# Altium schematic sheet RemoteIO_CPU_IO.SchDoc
size 431 x 279 mm; Date: Not shown in title block; ApprovedBy: Not shown in title block; CheckedBy: Not shown in title block; Author: Not shown in title block; CompanyName: Not shown in title block; Engineer: Not shown in title block; Organization: Not shown in title block; Address1: Not shown in title block; Address2: Not shown in title block; Address3: Not shown in title block; Address4: Not shown in title block; DocumentNumber: 5; Revision: Use project parameter SCH_Rev; SheetNumber: 5; SheetTotal: 14; PageSetup: Record=PageOptions¦CenterHorizontal=True¦CenterVertical=True¦PrintScale=1.00¦XCorrection=1.00¦YCorrection=1.00¦PrintKind=0¦BorderSize=5000000¦LeftOffset=0¦BottomOffset=0¦Orientation=2¦PaperLength=1000¦PaperWidth=1000¦Scale=100¦PaperSource=15¦PrintQuality=600¦MediaType=1¦DitherType=10¦PaperKind=Letter¦PrintScaleMode=1
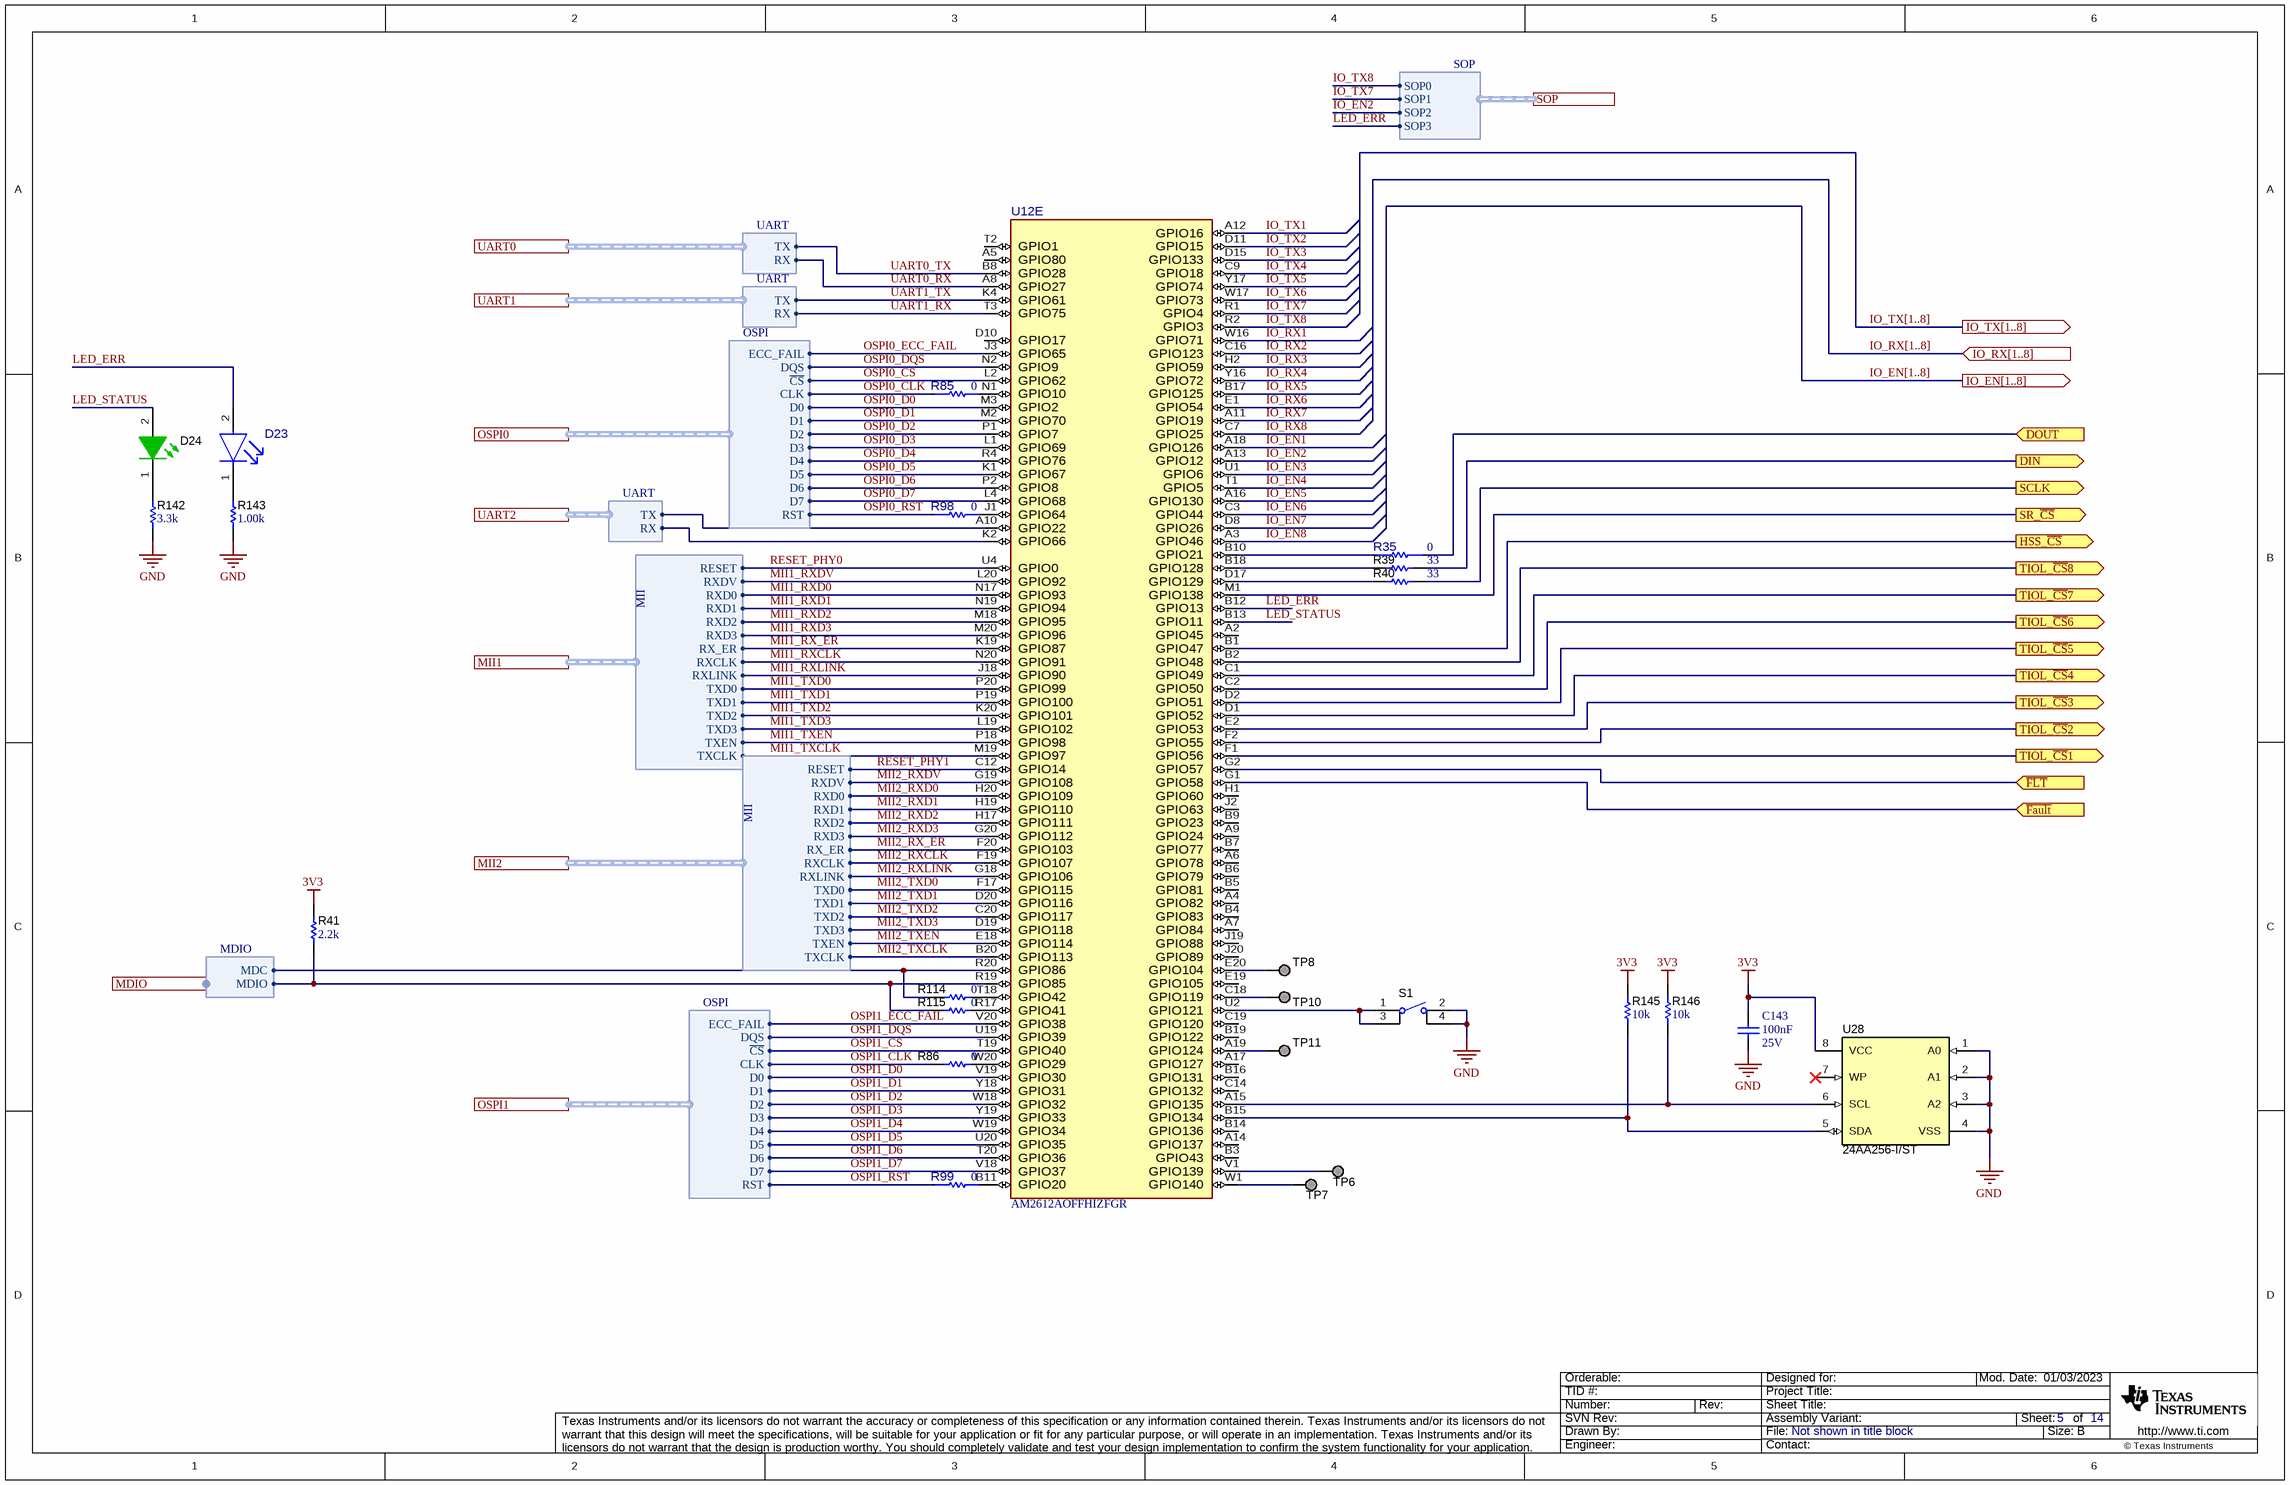
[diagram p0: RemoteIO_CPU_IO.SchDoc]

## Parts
C143  Cap_F: 100nF  Rated Voltage (DC): 25V  [WCAP-CSGP_0402_L1W0.5H0.5]  (hidden comment: 885012105018)
D23  150040RS73240  [FP-150040RS73220_0402-MFG]  (value not drawn)
D24  150040GS73240  [WL-SMCC_0402_Green]  (value not drawn)
R35  value 0  [FP-CRCW04020000Z0EDC_0402-MFG]  (hidden comment: CRCW04020000Z0EDC)
R39  ValueDisplayed: 33  [0402]  (hidden comment: CRCW040233R0JNED)
R40  ValueDisplayed: 33  [0402]  (hidden comment: CRCW040233R0JNED)
R41  ValueDisplayed: 2.2k  [0402]  (hidden comment: CRCW04022K20JNED)
R85  value 0  [FP-CRCW04020000Z0EDC_0402-MFG]  (hidden comment: CRCW04020000Z0EDC)
R86  ValueDisplayed: 0  [0201L]  (hidden comment: CRCW02010000Z0ED)
R98  value 0  [FP-CRCW04020000Z0EDC_0402-MFG]  (hidden comment: CRCW04020000Z0EDC)
R99  value 0  [FP-CRCW04020000Z0EDC_0402-MFG]  (hidden comment: CRCW04020000Z0EDC)
R114  ValueDisplayed: 0  [0201L]  (hidden comment: CRCW02010000Z0ED)
R115  ValueDisplayed: 0  [0201L]  (hidden comment: CRCW02010000Z0ED)
R142  ValueDisplayed: 3.3k  [0402]  (hidden comment: CRCW04023K30JNED)
R143  ValueDisplayed: 1.00k  [0402]  (hidden comment: CRCW04021K00FKED)
R145  ValueDisplayed: 10k  [0402]  (hidden comment: CRCW040210K0JNED)
R146  ValueDisplayed: 10k  [0402]  (hidden comment: CRCW040210K0JNED)
S1  434153017835  [SW_434153017835]  (value not drawn)
TP6  TESTPOINT  [TP_25MIL-SMT]  (value not drawn)  (no BOM)
TP7  TESTPOINT  [TP_25MIL-SMT]  (value not drawn)  (no BOM)
TP8  TESTPOINT  [TP_25MIL-SMT]  (value not drawn)  (no BOM)
TP10  TESTPOINT  [TP_25MIL-SMT]  (value not drawn)  (no BOM)
TP11  TESTPOINT  [TP_25MIL-SMT]  (value not drawn)  (no BOM)
U12  AM2612AOFFHIZFGR  [ZFG0304A-MFG]  (part E of 7)
U28  24AA256-I/ST  [TSSOP-8]

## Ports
DIN (out), DOUT (in), HSS_~{CS} (out), IO_EN[1..8] (out), IO_RX[1..8] (in), IO_TX[1..8] (out), MDIO (harness MDIO), MII1 (harness MII), MII2 (harness MII), OSPI0 (harness OSPI), OSPI1 (harness OSPI), SCLK (out), SOP (harness SOP), SR_~{CS} (out), TIOL_~{CS}1 (out), TIOL_~{CS}2 (out), TIOL_~{CS}3 (out), TIOL_~{CS}4 (out), TIOL_~{CS}5 (out), TIOL_~{CS}6 (out), TIOL_~{CS}7 (out), TIOL_~{CS}8 (out), UART0 (harness UART), UART1 (harness UART), UART2 (harness UART), ~{Fault} (in), ~{FLT} (in)

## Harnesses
MII: RXDV, RXD0, RXD1, RXD2, RXD3, RX_ER, RXCLK, RXLINK, TXD0, TXD1, TXD2, TXD3, TXEN, TXCLK, RESET
MDIO: MDC, MDIO
UART: TX, RX
OSPI: ~{CS}, CLK, D0, D1, D2, D3, D4, D5, D6, D7, DQS, ECC_FAIL, RST
SOP: SOP0, SOP1, SOP2, SOP3

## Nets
3V3: C143.2 R41.1 R145.1 R146.1 U28.8(VCC)
GND: C143.1 R142.1 R143.1 S1.2 S1.4 U28.1(A0) U28.2(A1) U28.3(A2) U28.4(VSS)
~{Fault}: U12.G1(GPIO58) ; port ~{Fault}
~{FLT}: U12.G2(GPIO57) ; port ~{FLT}
DIN: R39.2 ; port DIN
DOUT: R35.1 ; port DOUT
HSS_~{CS}: U12.B1(GPIO47) ; port HSS_~{CS}
IO_EN1: U12.A18(GPIO126)
IO_EN2: U12.A13(GPIO12) ; port SOP.SOP2
IO_EN3: U12.U1(GPIO6)
IO_EN4: U12.T1(GPIO5)
IO_EN5: U12.A16(GPIO130)
IO_EN6: U12.C3(GPIO44)
IO_EN7: U12.D8(GPIO26)
IO_EN8: U12.A3(GPIO46)
IO_RX1: U12.W16(GPIO71)
IO_RX2: U12.C16(GPIO123)
IO_RX3: U12.H2(GPIO59)
IO_RX4: U12.Y16(GPIO72)
IO_RX5: U12.B17(GPIO125)
IO_RX6: U12.E1(GPIO54)
IO_RX7: U12.A11(GPIO19)
IO_RX8: U12.C7(GPIO25)
IO_TX1: U12.A12(GPIO16)
IO_TX2: U12.D11(GPIO15)
IO_TX3: U12.D15(GPIO133)
IO_TX4: U12.C9(GPIO18)
IO_TX5: U12.Y17(GPIO74)
IO_TX6: U12.W17(GPIO73)
IO_TX7: U12.R1(GPIO4) ; port SOP.SOP1
IO_TX8: U12.R2(GPIO3) ; port SOP.SOP0
LED_ERR: D23.2(ANODE) U12.B12(GPIO13) ; port SOP.SOP3
LED_STATUS: D24.2(A) U12.B13(GPIO11)
MII1_RX_ER: U12.K19(GPIO87) ; port MII1.RX_ER
MII1_RXCLK: U12.N20(GPIO91) ; port MII1.RXCLK
MII1_RXD0: U12.N17(GPIO93) ; port MII1.RXD0
MII1_RXD1: U12.N19(GPIO94) ; port MII1.RXD1
MII1_RXD2: U12.M18(GPIO95) ; port MII1.RXD2
MII1_RXD3: U12.M20(GPIO96) ; port MII1.RXD3
MII1_RXDV: U12.L20(GPIO92) ; port MII1.RXDV
MII1_RXLINK: U12.J18(GPIO90) ; port MII1.RXLINK
MII1_TXCLK: U12.M19(GPIO97) ; port MII1.TXCLK
MII1_TXD0: U12.P20(GPIO99) ; port MII1.TXD0
MII1_TXD1: U12.P19(GPIO100) ; port MII1.TXD1
MII1_TXD2: U12.K20(GPIO101) ; port MII1.TXD2
MII1_TXD3: U12.L19(GPIO102) ; port MII1.TXD3
MII1_TXEN: U12.P18(GPIO98) ; port MII1.TXEN
MII2_RX_ER: U12.F20(GPIO103) ; port MII2.RX_ER
MII2_RXCLK: U12.F19(GPIO107) ; port MII2.RXCLK
MII2_RXD0: U12.H20(GPIO109) ; port MII2.RXD0
MII2_RXD1: U12.H19(GPIO110) ; port MII2.RXD1
MII2_RXD2: U12.H17(GPIO111) ; port MII2.RXD2
MII2_RXD3: U12.G20(GPIO112) ; port MII2.RXD3
MII2_RXDV: U12.G19(GPIO108) ; port MII2.RXDV
MII2_RXLINK: U12.G18(GPIO106) ; port MII2.RXLINK
MII2_TXCLK: U12.B20(GPIO113) ; port MII2.TXCLK
MII2_TXD0: U12.F17(GPIO115) ; port MII2.TXD0
MII2_TXD1: U12.D20(GPIO116) ; port MII2.TXD1
MII2_TXD2: U12.C20(GPIO117) ; port MII2.TXD2
MII2_TXD3: U12.D19(GPIO118) ; port MII2.TXD3
MII2_TXEN: U12.E18(GPIO114) ; port MII2.TXEN
OSPI0_~{CS}: U12.L2(GPIO62) ; port OSPI0.~{CS}
OSPI0_CLK: R85.1 ; port OSPI0.CLK
OSPI0_D0: U12.M3(GPIO2) ; port OSPI0.D0
OSPI0_D1: U12.M2(GPIO70) ; port OSPI0.D1
OSPI0_D2: U12.P1(GPIO7) ; port OSPI0.D2
OSPI0_D3: U12.L1(GPIO69) ; port OSPI0.D3
OSPI0_D4: U12.R4(GPIO76) ; port OSPI0.D4
OSPI0_D5: U12.K1(GPIO67) ; port OSPI0.D5
OSPI0_D6: U12.P2(GPIO8) ; port OSPI0.D6
OSPI0_D7: U12.L4(GPIO68) ; port OSPI0.D7
OSPI0_DQS: U12.N2(GPIO9) ; port OSPI0.DQS
OSPI0_ECC_FAIL: U12.J3(GPIO65) ; port OSPI0.ECC_FAIL
OSPI0_RST: R98.1 ; port OSPI0.RST
OSPI1_~{CS}: U12.T19(GPIO40) ; port OSPI1.~{CS}
OSPI1_CLK: R86.1 ; port OSPI1.CLK
OSPI1_D0: U12.V19(GPIO30) ; port OSPI1.D0
OSPI1_D1: U12.Y18(GPIO31) ; port OSPI1.D1
OSPI1_D2: U12.W18(GPIO32) ; port OSPI1.D2
OSPI1_D3: U12.Y19(GPIO33) ; port OSPI1.D3
OSPI1_D4: U12.W19(GPIO34) ; port OSPI1.D4
OSPI1_D5: U12.U20(GPIO35) ; port OSPI1.D5
OSPI1_D6: U12.T20(GPIO36) ; port OSPI1.D6
OSPI1_D7: U12.V18(GPIO37) ; port OSPI1.D7
OSPI1_DQS: U12.U19(GPIO39) ; port OSPI1.DQS
OSPI1_ECC_FAIL: U12.V20(GPIO38) ; port OSPI1.ECC_FAIL
OSPI1_RST: R99.1 ; port OSPI1.RST
RESET_PHY0: U12.U4(GPIO0) ; port MII1.RESET
RESET_PHY1: U12.C12(GPIO14) ; port MII2.RESET
SCLK: R40.2 ; port SCLK
SR_~{CS}: U12.M1(GPIO138) ; port SR_~{CS}
TIOL_~{CS}1: U12.F1(GPIO56) ; port TIOL_~{CS}1
TIOL_~{CS}2: U12.F2(GPIO55) ; port TIOL_~{CS}2
TIOL_~{CS}3: U12.E2(GPIO53) ; port TIOL_~{CS}3
TIOL_~{CS}4: U12.D1(GPIO52) ; port TIOL_~{CS}4
TIOL_~{CS}5: U12.D2(GPIO51) ; port TIOL_~{CS}5
TIOL_~{CS}6: U12.C2(GPIO50) ; port TIOL_~{CS}6
TIOL_~{CS}7: U12.C1(GPIO49) ; port TIOL_~{CS}7
TIOL_~{CS}8: U12.B2(GPIO48) ; port TIOL_~{CS}8
UART0_RX: U12.A8(GPIO27) ; port UART0.RX
UART0_TX: U12.B8(GPIO28) ; port UART0.TX
UART1_RX: U12.T3(GPIO75) ; port UART1.RX
UART1_TX: U12.K4(GPIO61) ; port UART1.TX
NetD23_1: D23.1(CATHODE) R143.2
NetD24_1: D24.1(K) R142.2
NetR35_2: R35.2 U12.B10(GPIO21)
NetR39_1: R39.1 U12.B18(GPIO128)
NetR40_1: R40.1 U12.D17(GPIO129)
NetR41_2: R41.2 R115.1 U12.R19(GPIO85) ; port MDIO.MDIO
NetR85_2: R85.2 U12.N1(GPIO10)
NetR86_2: R86.2 U12.W20(GPIO29)
NetR98_2: R98.2 U12.J1(GPIO64)
NetR99_2: R99.2 U12.B11(GPIO20)
NetR114_1: R114.1 U12.R20(GPIO86) ; port MDIO.MDC
NetR114_2: R114.2 U12.T18(GPIO42)
NetR115_2: R115.2 U12.R17(GPIO41)
NetR145_2: R145.2 U12.B15(GPIO134) U28.5(SDA)
NetR146_2: R146.2 U12.A15(GPIO135) U28.6(SCL)
NetS1_1: S1.1 S1.3 U12.U2(GPIO121)
NetTP6_1: TP6.1 U12.V1(GPIO139)
NetTP7_1: TP7.1 U12.W1(GPIO140)
NetTP8_1: TP8.1 U12.E20(GPIO104)
NetTP10_1: TP10.1 U12.C18(GPIO119)
NetTP11_1: TP11.1 U12.A19(GPIO124)
NetU12_A10: U12.A10(GPIO22) ; port UART2.TX
NetU12_K2: U12.K2(GPIO66) ; port UART2.RX

Not connected (* = marked no-connect by the designer): U12 A2(GPIO45) A4(GPIO82) A5(GPIO80) A6(GPIO78) A7(GPIO84) A9(GPIO24) A14(GPIO137) A17(GPIO127) B3(GPIO43) B4(GPIO83) B5(GPIO81) B6(GPIO79) B7(GPIO77) B9(GPIO23) B14(GPIO136) B16(GPIO131) B19(GPIO122) C14(GPIO132) C19(GPIO120) D10(GPIO17) E19(GPIO105) H1(GPIO60) J2(GPIO63) J19(GPIO88) J20(GPIO89) T2(GPIO1); U28 7(WP)*

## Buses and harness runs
bus IO_EN[1..8] = port IO_EN[1..8]
bus IO_RX[1..8] = port IO_RX[1..8]
bus IO_TX[1..8] = port IO_TX[1..8]

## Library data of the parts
C143 = CMP-0119143-1: WCAP-CSGP Multilayer Ceramic Chip Capacitor, General Purpose, size 0402, X5R, 100nF, 25VDC; Manufacturer: Wurth Elektronik; PartNumber: '885012105018; Capacitance Tolerance: +/-20%; Case/Size Code: 0402; Dissipation Factor: 10%; Insulation Resistance: 5GOhm; Technical Reference: X5R0402104M025DFCT10000
D23 = CMP-0122246-1: Red 624nm LED Indication - Discrete 2V 0402 (1005 Metric); Manufacturer: Wurth; Angle: 120°; LambdaP: 632nm; Power_TotalModule: 48mW; SizeZ_mm: 0.35mm; Tjmax_C: 115°C; Vr_V: 5V; AEC Qualified: No; Forward Current: 20mA; Led Orientation: Top View; Luminous Intensity: 110mcd
D24 = CMP-0081765-2: LED, Green, SMD; Manufacturer: Wurth Elektronik; Vr_V: 5V; Io_A: 20mA; Tjmax_C: 95°C; Ir_A: 10µA; Power_TotalModule: 99mW; Value2: 3.2V; SizeArea_mm2: 0.5; SizeX_mm: 1; Value1: 0.099W; Angle: 120; Type: InGaN; SizeAreaWB_mm2: 3
R35 R85 R98 R99 = CMP-0093210-1: Jumper 0.063W, 1/16W Chip Resistor 0402 (1005 Metric) - Thick Film; Manufacturer: Vishay; AEC Qualified: No; VDC_V: 50V; Power_W: 63mW; SizeZ_mm: 0.35mm
R39 R40 = CMP-0026908-3: RES, 33, 5%, 0.063 W, AEC-Q200 Grade 0, 0402; Manufacturer: Vishay-Dale; Power_W: 63mW; TempCo: 200 ppm/C; Value_Code: 33R0; Value: 33; EIA_Code: E24; SizeX_mm: 1; SizeY_mm: 0.5; SizeZ_mm: 0.6; Value2: 0.063W; AEC Qualified: Y; VDC_V: 50V; AEC Category: Q200; AEC Grade: 0
R41 = CMP-0026890-5: RES, 2.2 k, 5%, 0.063 W, AEC-Q200 Grade 0, 0402; Manufacturer: Vishay-Dale; Power_W: 63mW; TempCo: 200 ppm/C; Value_Code: 2k20; Value: 2.2k; EIA_Code: E24; SizeX_mm: 1; SizeY_mm: 0.5; SizeZ_mm: 0.6; Value2: 0.063W; AEC Qualified: Y; VDC_V: 50V; AEC Category: Q200; AEC Grade: 0
R86 R114 R115 = CMP-0027008-4: RES, 0, 5%, 0.05 W, 0201; Manufacturer: Vishay-Dale; Power_W: 50mW; TempCo: ppm/C; Value_Code: 0000; Value: 0; EIA_Code: E24; SizeX_mm: 0.6; SizeY_mm: 0.3; SizeZ_mm: 0.26; Value2: 0.05W; SizeArea_mm2: 0.18; AEC Qualified: N; AEC Category: Q200
R142 = CMP-0026918-5: RES, 3.3 k, 5%, 0.063 W, AEC-Q200 Grade 0, 0402; Manufacturer: Vishay-Dale; Power_W: 63mW; TempCo: 200 ppm/C; Value_Code: 3k30; Value: 3.3k; EIA_Code: E24; SizeX_mm: 1; SizeY_mm: 0.5; SizeZ_mm: 0.6; Value2: 0.063W; AEC Qualified: Y; VDC_V: 50V; AEC Category: Q200; AEC Grade: 0
R143 = CMP-0026071-3: RES, 1.00 k, 1%, 0.063 W, AEC-Q200 Grade 0, 0402; Manufacturer: Vishay-Dale; Power_W: 63mW; TempCo: 100 ppm/C; Value_Code: 1k00; Value: 1.00k; EIA_Code: E96; Res_ohm: 1k; SizeX_mm: 1; SizeY_mm: 0.5; SizeZ_mm: 0.6; Value2: 0.063W; AEC Qualified: Y; VDC_V: 50V; AEC Category: Q200; AEC Grade: 0
R145 R146 = CMP-0026825-5: RES, 10 k, 5%, 0.063 W, AEC-Q200 Grade 0, 0402; Manufacturer: Vishay-Dale; Power_W: 63mW; TempCo: 200 ppm/C; Value_Code: 10k0; Value: 10k; EIA_Code: E24; SizeX_mm: 1; SizeY_mm: 0.5; SizeZ_mm: 0.6; Value2: 0.063W; AEC Qualified: Y; VDC_V: 50V; AEC Category: Q200; AEC Grade: 0
S1 = CMP-0002302-1: Switch, SPST, Off-Mom, 0.05 A, 12 VDC, SMD; Manufacturer: Wurth Elektronik; CurrentRating_mA: 50A; PositionCount: 1; SizeX_mm: 4.3; SizeY_mm: 2.9; SizeZ_mm: 1.9; SizeArea_mm2: 12.47; VDC_V: 12V; SizeAreaWB_mm2: 20.67
TP6-TP8 TP10 TP11 = CMP-0078143-4: TEST POINT.  No entry in BOM.
U12 = CMP-0126016-1: ARM® Cortex®-R5F Sitara™ Microcontroller IC 32-Bit Dual-Core 500MHz 512KB (512K x 8) Tightly Coupled Memory (TCM) 304-NFBGA (13.25x13.25); Manufacturer: Texas Instruments; SizeZ_mm: 1.3mm; AEC Qualified: No; Core Architecture: ARM Cortex-R5F; Data Bus Width: 32bits; Interface: I2C,SPI,UART,CAN,USB,LIN,Ethernet; Max Supply Voltage: 3.465V; Min Supply Voltage: 1.14V; Number Of A/D Converters: 3; Number Of Adc Channels: 7; Number Of Cores: 2; Number Of Ethernet Channels: 1; Number Of I/Os: 141; Number Of Pwm Channels: 10; Number Of Spi Channels: 4; Number Of Uart Channels: 6; Ram Size: 1.5MBytes; Standoff Height: 0.23mm; TJmax_C: +125°C
U28 = CMP-0005248-2: 256K I2C™ CMOS Serial EEPROM, TSSOP-8; Manufacturer: Microchip; SizeAreaWB_mm2: 42; SizeZ_mm: 1.2; SizeX_mm: 6.4; SizeY_mm: 3; SizeArea_mm2: 19.2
